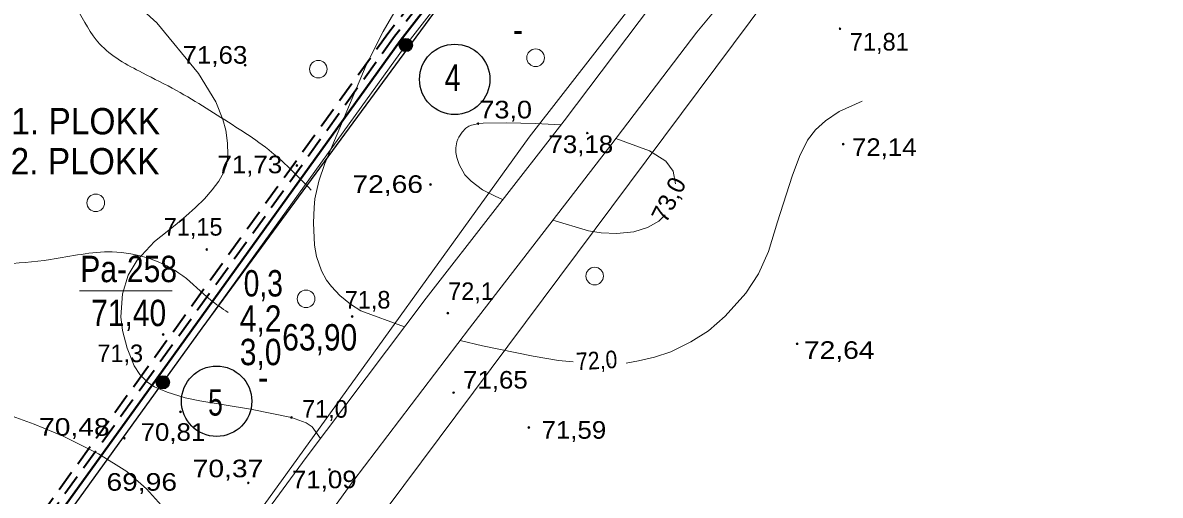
# Model space of a CAD drawing. Extents: x 628176 to 629009, y 6439913 to 6440496.
# Drawn here: x 628597 to 628726.4, y 6440288.3 to 6440342 of the extents above; entities that cross this region are included whole.
import ezdxf
from ezdxf.enums import TextEntityAlignment as Align

# ---------------------------------------------------------------- set-up
doc = ezdxf.new("R2010")
doc.units = 0
doc.header["$LTSCALE"] = 0.8
doc.linetypes.add('MEDIUM_DASHED', pattern=[4.5, 3, -1.5])
for name, color, linetype, lineweight in [('1', 7, 'Continuous', 13), ('10', 7, 'Continuous', 25), ('11', 7, 'Continuous', 13), ('12', 7, 'Continuous', 13), ('14', 7, 'Continuous', 25), ('16', 7, 'Continuous', 13), ('21', 7, 'MEDIUM_DASHED', 35), ('3', 7, 'Continuous', 13), ('6', 7, 'Continuous', 13)]:
    doc.layers.add(name, color=color, linetype=linetype, lineweight=lineweight)

msp = doc.modelspace()

# ---------------------------------------------------------------- hatches: boundary and pattern name
at = {"layer": '1'}
for points in [[(628690.0745, 6440341.3184, 1), (628689.8745, 6440341.3184, 1)], [(628622.406, 6440337.1829, 1), (628622.206, 6440337.1829, 1)], [(628648.8966, 6440330.5307, 1), (628648.6966, 6440330.5307, 1)], [(628661.3325, 6440329.4635, 1), (628661.1325, 6440329.4635, 1)], [(628690.4456, 6440328.2067, 1), (628690.2456, 6440328.2067, 1)], [(628628.2942, 6440325.7706, 1), (628628.0942, 6440325.7706, 1)], [(628643.4902, 6440323.614, 1), (628643.2902, 6440323.614, 1)], [(628618.0329, 6440316.2227, 1), (628617.8329, 6440316.2227, 1)], [(628634.5857, 6440308.61, 1), (628634.3857, 6440308.61, 1)], [(628645.4655, 6440308.9909, 1), (628645.2655, 6440308.9909, 1)], [(628613.0795, 6440306.5571, 1), (628612.8795, 6440306.5571, 1)], [(628685.1935, 6440305.5062, 1), (628684.9935, 6440305.5062, 1)], [(628646.1214, 6440299.9489, 1), (628645.9214, 6440299.9489, 1)], [(628615.0529, 6440297.7688, 1), (628614.8529, 6440297.7688, 1)], [(628627.6731, 6440297.1294, 1), (628627.4731, 6440297.1294, 1)], [(628654.6812, 6440295.989, 1), (628654.4812, 6440295.989, 1)], [(628608.6637, 6440294.7599, 1), (628608.4637, 6440294.7599, 1)], [(628631.9945, 6440291.2134, 1), (628631.7945, 6440291.2134, 1)], [(628622.7658, 6440289.6835, 1), (628622.5658, 6440289.6835, 1)]]:
    msp.add_hatch(color=256, dxfattribs=at).paths.add_polyline_path(points)
at = {"layer": '10'}
for points in [[(628641.3382, 6440339.469, 1), (628639.8382, 6440339.469, 1)], [(628613.7008, 6440301.1229, 1), (628612.2008, 6440301.1229, 1)]]:
    msp.add_hatch(color=256, dxfattribs=at).paths.add_polyline_path(points)

# ---------------------------------------------------------------- linework, layer by layer
at = {"layer": '1'}
for p, q in [((628673.69, 6440340.93), (628687.94, 6440358.07)), ((628658.58, 6440330.86), (628668.54, 6440344)), ((628663.89, 6440328.07), (628673.69, 6440340.93)), ((628642.89, 6440310.69), (628658.58, 6440330.86)), ((628647.84, 6440307.29), (628663.89, 6440328.07)), ((628629.23, 6440292.59), (628642.89, 6440310.69)), ((628634.56, 6440289.83), (628647.84, 6440307.29)), ((628613.8, 6440271.46), (628629.23, 6440292.59)), ((628619.08, 6440268.61), (628634.56, 6440289.83))]:
    msp.add_line(p, q, dxfattribs=at)
for centre, radius in [((628689.9745, 6440341.3184), 0.1), ((628655.3467, 6440338.0219), 1), ((628622.306, 6440337.1829), 0.1), ((628630.6352, 6440336.7248), 1), ((628648.7966, 6440330.5307), 0.1), ((628661.2325, 6440329.4635), 0.1), ((628690.3456, 6440328.2067), 0.1), ((628628.1942, 6440325.7706), 0.1), ((628643.3902, 6440323.614), 0.1), ((628605.3118, 6440321.5307), 1), ((628617.9329, 6440316.2227), 0.1), ((628662.0683, 6440313.2034), 1), ((628629.2356, 6440310.6182), 1), ((628634.4857, 6440308.61), 0.1), ((628645.3655, 6440308.9909), 0.1), ((628612.9795, 6440306.5571), 0.1), ((628685.0935, 6440305.5062), 0.1), ((628646.0214, 6440299.9489), 0.1), ((628614.9529, 6440297.7688), 0.1), ((628627.5731, 6440297.1294), 0.1), ((628654.5812, 6440295.989), 0.1), ((628608.5637, 6440294.7599), 0.1), ((628631.8945, 6440291.2134), 0.1), ((628622.6658, 6440289.6835), 0.1)]:
    msp.add_circle(centre, radius, dxfattribs=at)
at = {"layer": '10'}
for centre, radius in [((628640.5882, 6440339.469), 0.75), ((628646.1438, 6440335.567), 4), ((628619.0628, 6440298.9717), 4), ((628612.9508, 6440301.1229), 0.75)]:
    msp.add_circle(centre, radius, dxfattribs=at)
at = {"layer": '11'}
msp.add_lwpolyline([(628709.76, 6440416.52), (628665.41, 6440371.4), (628640.59, 6440339.47), (628612.95, 6440301.12), (628547.63, 6440210.77)], dxfattribs=at)
at = {"layer": '12'}
msp.add_line((628603.45, 6440311.51), (628614, 6440311.51), dxfattribs=at)
at = {"layer": '14'}
msp.add_lwpolyline([(628648.46, 6440349.59), (628617.39, 6440307.28), (628547.63, 6440210.77), (628497.5, 6440118.54), (628474.19, 6440080.39)], dxfattribs=at)
at = {"layer": '16'}
for points in [[(628602.3, 6440372.11), (628600.02, 6440366.27), (628598.73, 6440361.54), (628598.87, 6440354.51), (628600.45, 6440348.49), (628603.17, 6440343.62), (628605.75, 6440339.61), (628610.62, 6440336.31), (628614.49, 6440334.3), (628621.23, 6440330.15), (628624.24, 6440328.14), (628629.83, 6440322.98)], [(628550.39, 6440317.66), (628552.57, 6440316.38), (628560.31, 6440314.09), (628568.05, 6440313.52), (628583.1, 6440313.23), (628588.55, 6440313.95), (628594.43, 6440314.52), (628600.16, 6440315.09), (628607.18, 6440315.95), (628615.21, 6440313.23), (628618.36, 6440310.51), (628620.37, 6440309.07)]]:
    msp.add_spline(points, degree=3, dxfattribs=at)
at = {"layer": '21', "linetype": 'Continuous', "lineweight": 40}
msp.add_lwpolyline([(628708.01, 6440415.87), (628664.8, 6440371.93), (628639.95, 6440339.95), (628612.3, 6440301.59), (628546.94, 6440211.19)], dxfattribs=at)
at = {"layer": '21'}
for points in [[(628704.5, 6440414.58), (628663.6, 6440372.99), (628638.67, 6440340.91), (628611, 6440302.53), (628546.02, 6440212.64)], [(628706.25, 6440415.23), (628664.2, 6440372.46), (628639.31, 6440340.43), (628611.65, 6440302.06), (628547.03, 6440212.69)]]:
    msp.add_lwpolyline(points, dxfattribs=at)
at = {"layer": '3'}
for p, q in [((628612.27, 6440342), (628607.74, 6440346.1)), ((628637.99, 6440341), (628636.08, 6440337.18)), ((628636.08, 6440337.18), (628631.37, 6440326)), ((628648.8, 6440330.53), (628648.6, 6440330.49)), ((628661.38, 6440318.34), (628657.31, 6440319.56)), ((628661.38, 6440318.34), (628662.81, 6440318.13)), ((628676.9, 6440308.64), (628679.27, 6440311.26)), ((628675.01, 6440306.97), (628676.9, 6440308.64)), ((628657.94, 6440303.59), (628659.63, 6440303.44)), ((628663.55, 6440303.19), (628663.87, 6440303.21)), ((628667.07, 6440303.57), (628665.64, 6440303.31)), ((628613.42, 6440300), (628612, 6440300.62)), ((628615.47, 6440299.37), (628613.42, 6440300)), ((628627.57, 6440297.13), (628622.9, 6440298.09)), ((628627.57, 6440297.13), (628629.25, 6440296.51)), ((628629.93, 6440296.05), (628629.25, 6440296.51)), ((628629.93, 6440296.05), (628630.86, 6440294.75))]:
    msp.add_line(p, q, dxfattribs=at)
for points in [[(628682.96, 6440361.42), (628668.28, 6440358), (628665, 6440357), (628654, 6440353), (628649, 6440351), (628648, 6440350.55), (628645.58, 6440349.4), (628644.26, 6440348.69), (628643.52, 6440348.23), (628643, 6440347.81), (628642.36, 6440347.21), (628641.22, 6440346), (628639.74, 6440344), (628637.99, 6440341)], [(628612, 6440300.62), (628611.23, 6440301.12), (628610.32, 6440302), (628609.69, 6440303), (628608.87, 6440305), (628608.34, 6440307), (628608.17, 6440308.56), (628608.35, 6440311.2), (628609, 6440313.32), (628610.03, 6440315), (628612, 6440317.14), (628614.36, 6440319), (628615.56, 6440320), (628616.67, 6440321), (628617.69, 6440322), (628618.55, 6440323), (628619.32, 6440324), (628619.89, 6440325), (628620.23, 6440326), (628620.33, 6440327), (628620.31, 6440328.32), (628620.11, 6440329.78), (628619.78, 6440331), (628618.98, 6440333), (628617, 6440336.23), (628612.27, 6440342)], [(628679.27, 6440311.26), (628680.71, 6440313.45), (628681.83, 6440316), (628682.86, 6440319.38), (628684.55, 6440324.56), (628685.36, 6440326.8), (628686.29, 6440328.64), (628687.2, 6440329.82), (628688.33, 6440330.86), (628689.89, 6440331.91), (628692.49, 6440333.1)], [(628646.5, 6440328.77), (628646.62, 6440329), (628647, 6440329.58), (628647.43, 6440330), (628647.77, 6440330.23), (628648.07, 6440330.35), (628648.6, 6440330.49)], [(628648.8, 6440330.53), (628649.38, 6440330.57), (628652, 6440330.61), (628655.33, 6440330.53), (628658.2, 6440330.38)], [(628646.5, 6440328.77), (628646.39, 6440328.46), (628646.29, 6440327.77), (628646.29, 6440327.24), (628646.39, 6440326.69), (628646.64, 6440325.87), (628647.3, 6440324.71), (628648, 6440324), (628649.32, 6440323), (628650.75, 6440322.28), (628651.6, 6440321.89)], [(628671.27, 6440323.69), (628670.98, 6440325.12), (628670.18, 6440326.25), (628668.29, 6440327.45), (628664.49, 6440328.86)], [(628631.37, 6440326), (628630.7, 6440324), (628630.25, 6440322), (628630.14, 6440321.01)], [(628630.18, 6440316.7), (628630.08, 6440319.27), (628630.14, 6440321.01)], [(628670.08, 6440320.17), (628669.36, 6440319.46), (628668.09, 6440318.72), (628666.53, 6440318.25), (628664.6, 6440318.04), (628662.81, 6440318.13)], [(628632.12, 6440312), (628631.55, 6440312.74), (628631, 6440313.79), (628630.44, 6440315.44), (628630.18, 6440316.7)], [(628632.12, 6440312), (628633.09, 6440311), (628634.3, 6440310), (628635.46, 6440309.26), (628640.44, 6440307.45)], [(628667.07, 6440303.57), (628668.89, 6440304), (628670.75, 6440304.58), (628673, 6440305.74), (628675.01, 6440306.97)], [(628646.77, 6440305.88), (628649.32, 6440305.28), (628655.06, 6440304.08), (628657.94, 6440303.59)], [(628622.9, 6440298.09), (628617.15, 6440299), (628615.47, 6440299.37)], [(628611.1, 6440289), (628608.85, 6440291), (628605.61, 6440293), (628601.59, 6440295.01), (628598.29, 6440296.37), (628596.23, 6440297.14), (628594.2, 6440297.83), (628593.44, 6440298.03)], [(628611.1, 6440289), (628613.8, 6440286), (628615.13, 6440283.75)]]:
    msp.add_lwpolyline(points, dxfattribs=at)
at = {"layer": '6'}
for points in [[(628713.84, 6440420.66), (628737.18, 6440419.44), (628678.6, 6440359.86), (628654.6, 6440328.98), (628627.14, 6440290.88), (628627.14, 6440290.88), (628627.14, 6440290.88), (628562.66, 6440201.7), (628536.24, 6440148.38), (628489.22, 6440071.42), (628480.02, 6440052.78), (628457.03, 6440037.16), (628421.17, 6440028.67)], [(628753.89, 6440420.62), (628687.68, 6440352.8), (628636.46, 6440284.16), (628572.54, 6440195.74), (628546.32, 6440142.82), (628546.32, 6440142.82), (628546.32, 6440142.82), (628498.7, 6440064.9), (628484.24, 6440046.28), (628473.72, 6440036.18), (628464.05, 6440028.67)]]:
    msp.add_lwpolyline(points, dxfattribs=at)

# ---------------------------------------------------------------- texts
at = {"layer": '1'}
for s, p in [('71,81', (628691.1, 6440338.84)), ('71,15', (628613.04, 6440317.8)), ('72,1', (628645.4, 6440310.48)), ('71,8', (628633.63, 6440309.51)), ('71,3', (628605.49, 6440303.42)), ('71,0', (628628.77, 6440297.1))]:
    msp.add_text(s, height=2, dxfattribs=at).set_placement(p)
for s, width, p in [('71,63', 1.1, (628615.19, 6440337.35)), ('73,0', 1.15, (628648.95, 6440331.13)), ('73,18', 1.1, (628656.81, 6440327.19)), ('72,14', 1.1, (628691.33, 6440326.86)), ('71,73', 1.1, (628619.16, 6440324.89)), ('72,66', 1.2, (628634.51, 6440322.66)), ('72,64', 1.2, (628685.87, 6440303.79)), ('71,65', 1.1, (628647.09, 6440300.41)), ('70,48', 1.2, (628598.86, 6440295.05)), ('70,81', 1.1, (628610.41, 6440294.47)), ('71,59', 1.1, (628656.02, 6440294.71)), ('70,37', 1.2, (628616.34, 6440290.33)), ('69,96', 1.2, (628606.53, 6440288.8)), ('71,09', 1.1, (628627.63, 6440289.08))]:
    msp.add_text(s, height=2, dxfattribs=dict(at, width=width)).set_placement(p)
at = {"layer": '10'}
for s, width, p in [('4', 0.8, (628645.91, 6440334.26)), ('5', 0.75, (628618.93, 6440297.34))]:
    msp.add_text(s, height=3, dxfattribs=dict(at, width=width)).set_placement(p, align=Align.CENTER)
at = {"layer": '12'}
for s, width, p in [('-', 0.85, (628653.345, 6440339.75)), ('Pa-258', 0.85, (628609.055, 6440312.51)), ('0,3', 0.8, (628624.37, 6440310.88)), ('71,40', 0.85, (628609.055, 6440307.51)), ('4,2', 0.85, (628624.065, 6440306.87)), ('63,90', 0.85, (628630.79, 6440304.74)), ('3,0', 0.85, (628624.07, 6440303.07)), ('-', 0.9, (628624.345, 6440300.2))]:
    msp.add_text(s, height=3, dxfattribs=dict(at, width=width)).set_placement(p, align=Align.CENTER)
at = {"layer": '21', "width": 0.95}
for s, p in [('1. PLOKK', (628604.165, 6440329.31)), ('2. PLOKK', (628604.095, 6440324.76))]:
    msp.add_text(s, height=3, dxfattribs=at).set_placement(p, align=Align.CENTER)
at = {"layer": '3'}
msp.add_text('73,0', height=2, rotation=63.094, dxfattribs=at).set_placement((628670.2, 6440319.13))
at = {"layer": '3', "width": 0.9}
msp.add_text('72,0', height=2, rotation=3.482, dxfattribs=at).set_placement((628660.02, 6440302.48))

doc.saveas('drawing.dxf')
